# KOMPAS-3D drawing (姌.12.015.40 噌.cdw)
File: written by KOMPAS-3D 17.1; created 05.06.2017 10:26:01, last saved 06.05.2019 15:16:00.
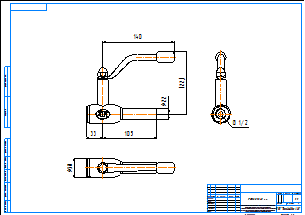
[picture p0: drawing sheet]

Sheet 1: A2, landscape

Title block, sheet 1: name: КШ.12.015.40 рс; material: Внимание! Данный продукт является объектом авторского права ООО «Торговый Дом АДЛ». / Запрещается изменение, копирование, распространение / (в том числе путем копирования на другие сайты и ресурсы в Интернете) / или любое иное использование информации и объектов без предварительного / согласия правообладателя (ООО «Торговый Дом АДЛ»).; sheets: 1; organisation: ООО "Торговый дом АДЛ"; sheet format: A2; stored path: C:\Users\kka\KOMPAS_Work\Модели кранов для исследований\Все краники\Редуцированный резьба-сварка ШК БИВАЛ\КШ.02.015.40 рс.cdw

Views: Вид 1, Проекционный вид 2, Проекционный вид 3
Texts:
  Klimkovich
  ADL
Dimensions and other numbers on the sheet: 105; 122,1; 140; 22; 33; 38; 1:1; 1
